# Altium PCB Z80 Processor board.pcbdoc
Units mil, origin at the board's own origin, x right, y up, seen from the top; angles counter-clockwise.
Board outline 3050 x 2500 mil, 4 copper layers (TopLayer, GroundPlane, PowerNetsPlane, BottomLayer); 36 components, 88 nets, 434 pads, 178 vias.
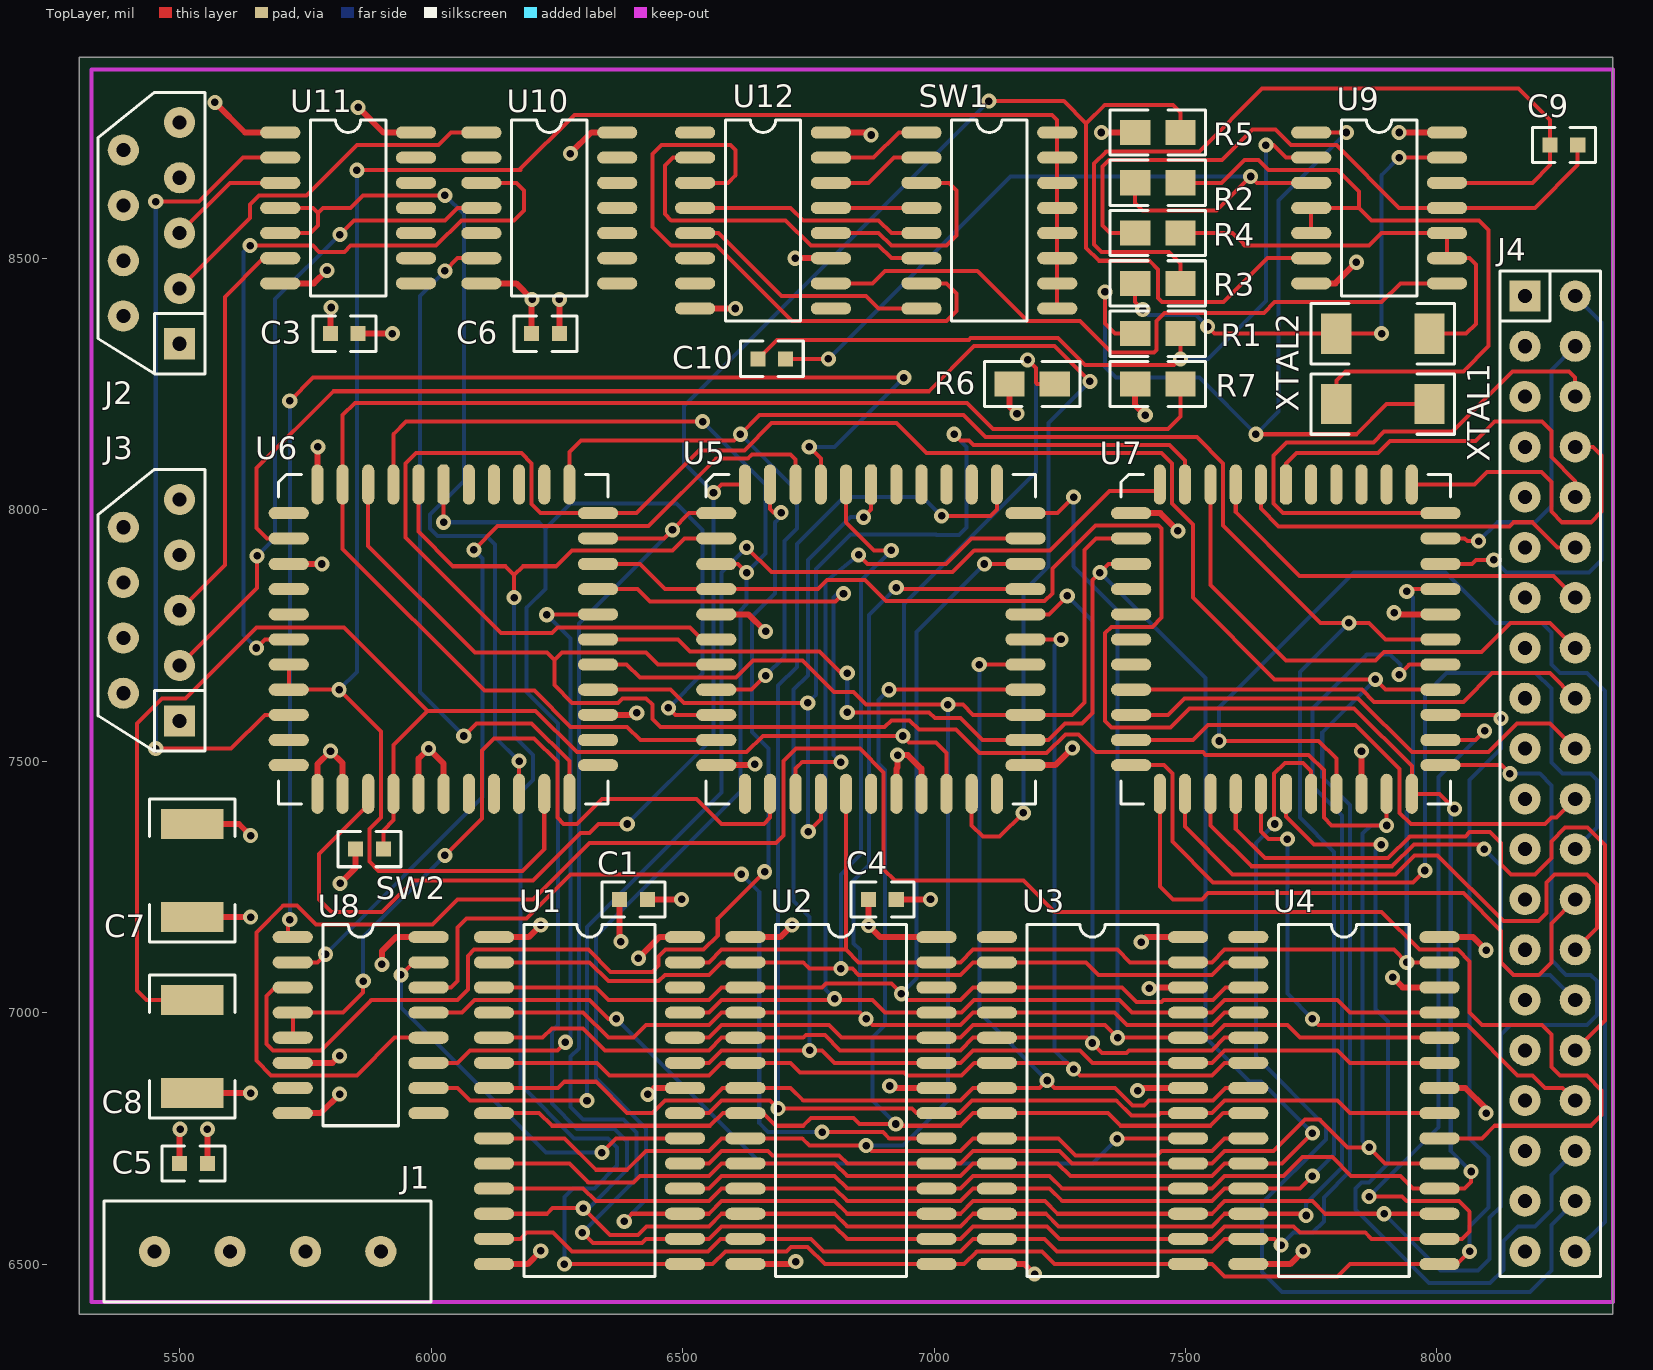
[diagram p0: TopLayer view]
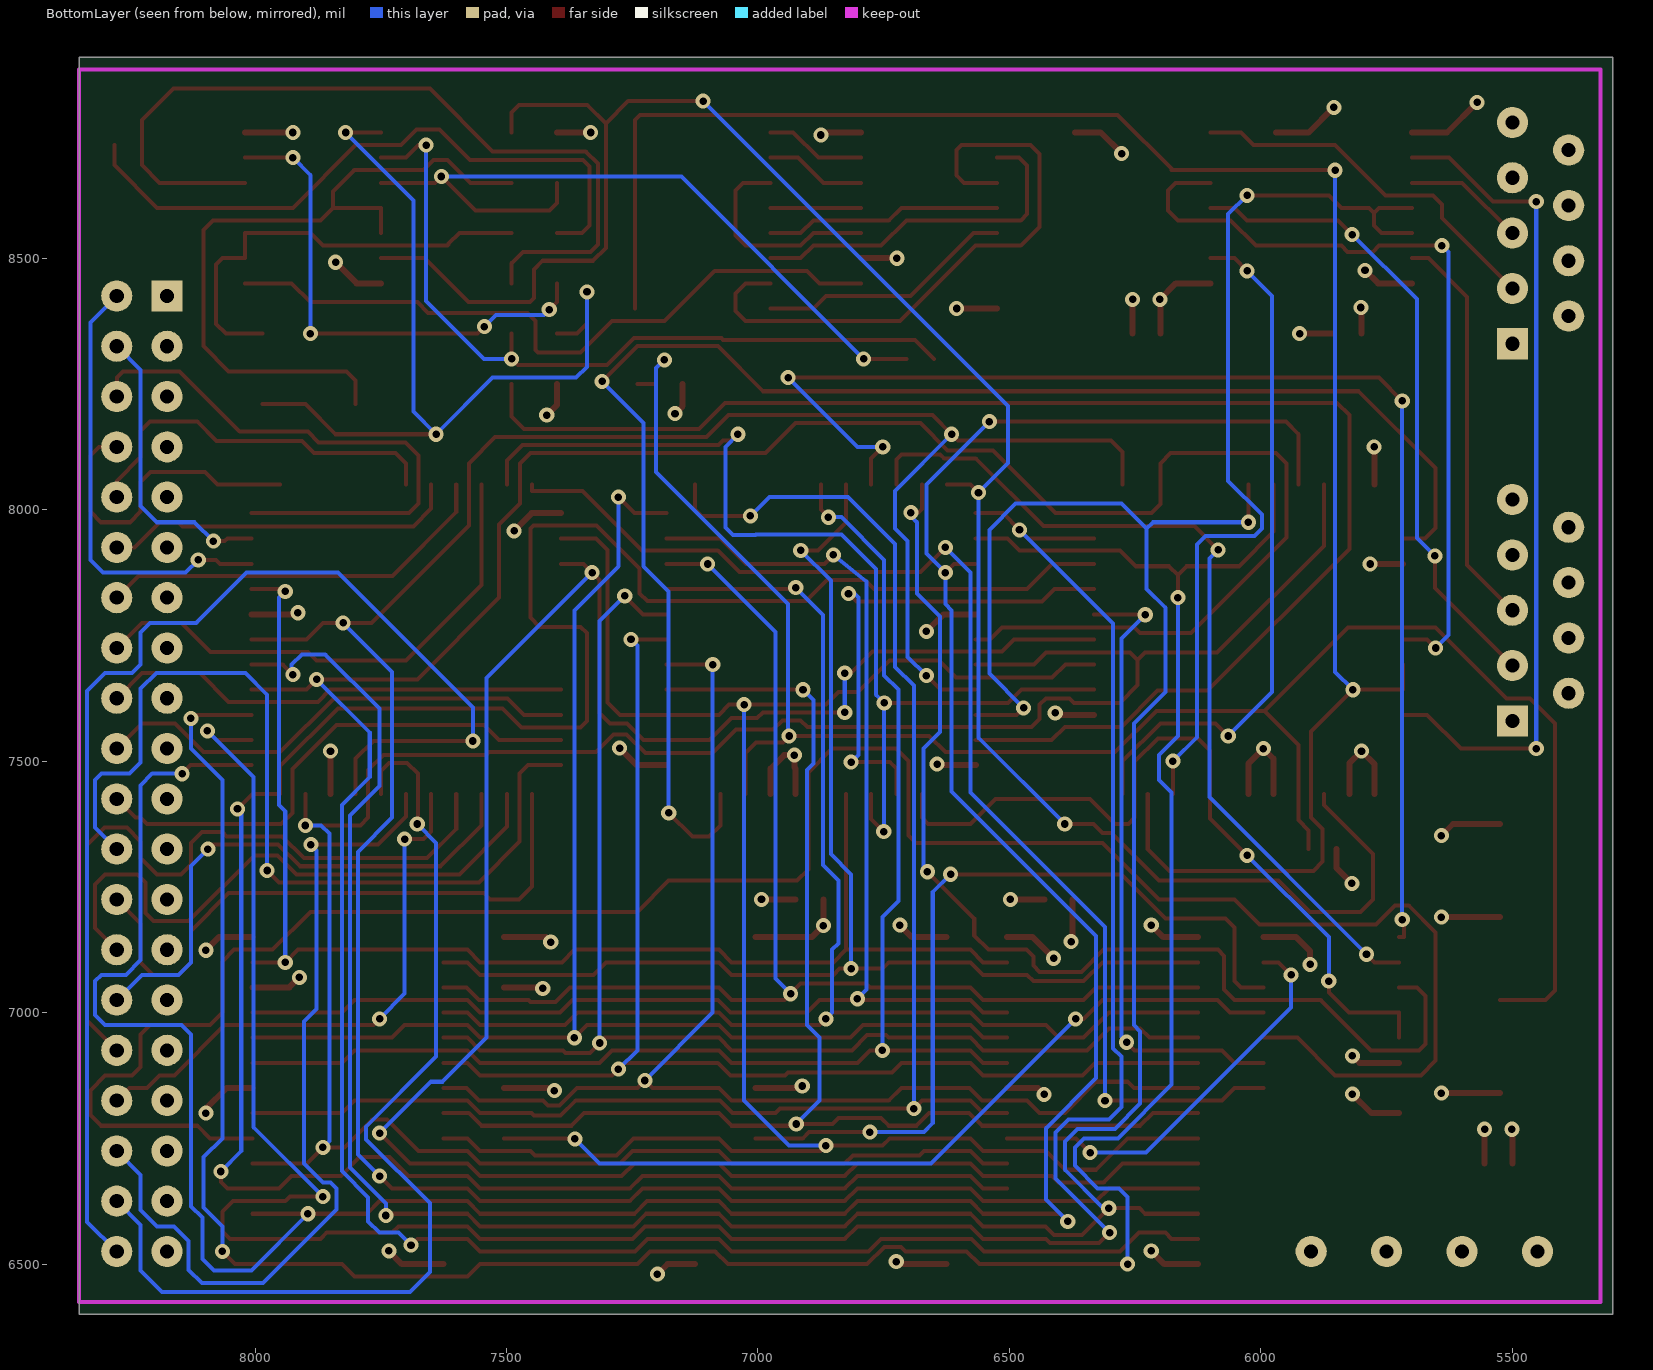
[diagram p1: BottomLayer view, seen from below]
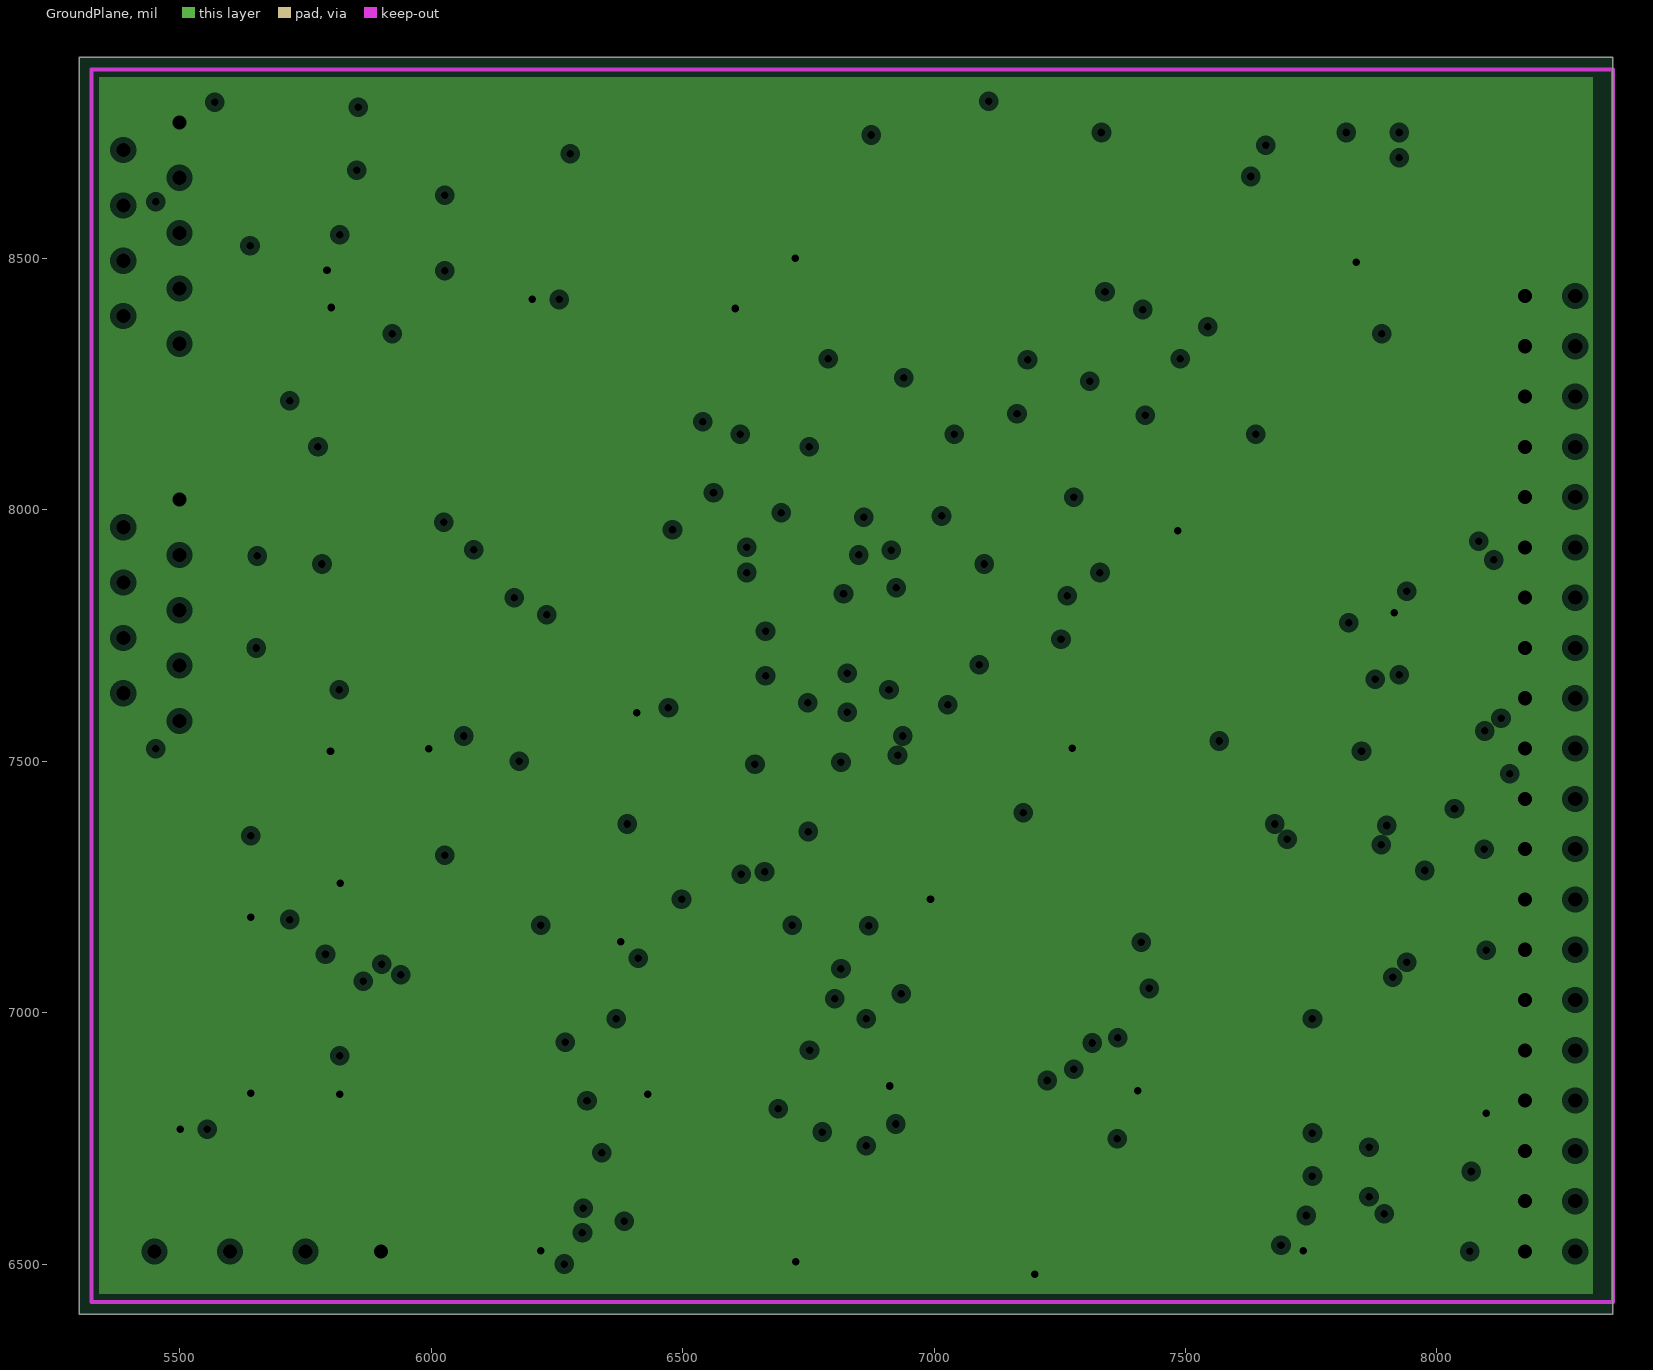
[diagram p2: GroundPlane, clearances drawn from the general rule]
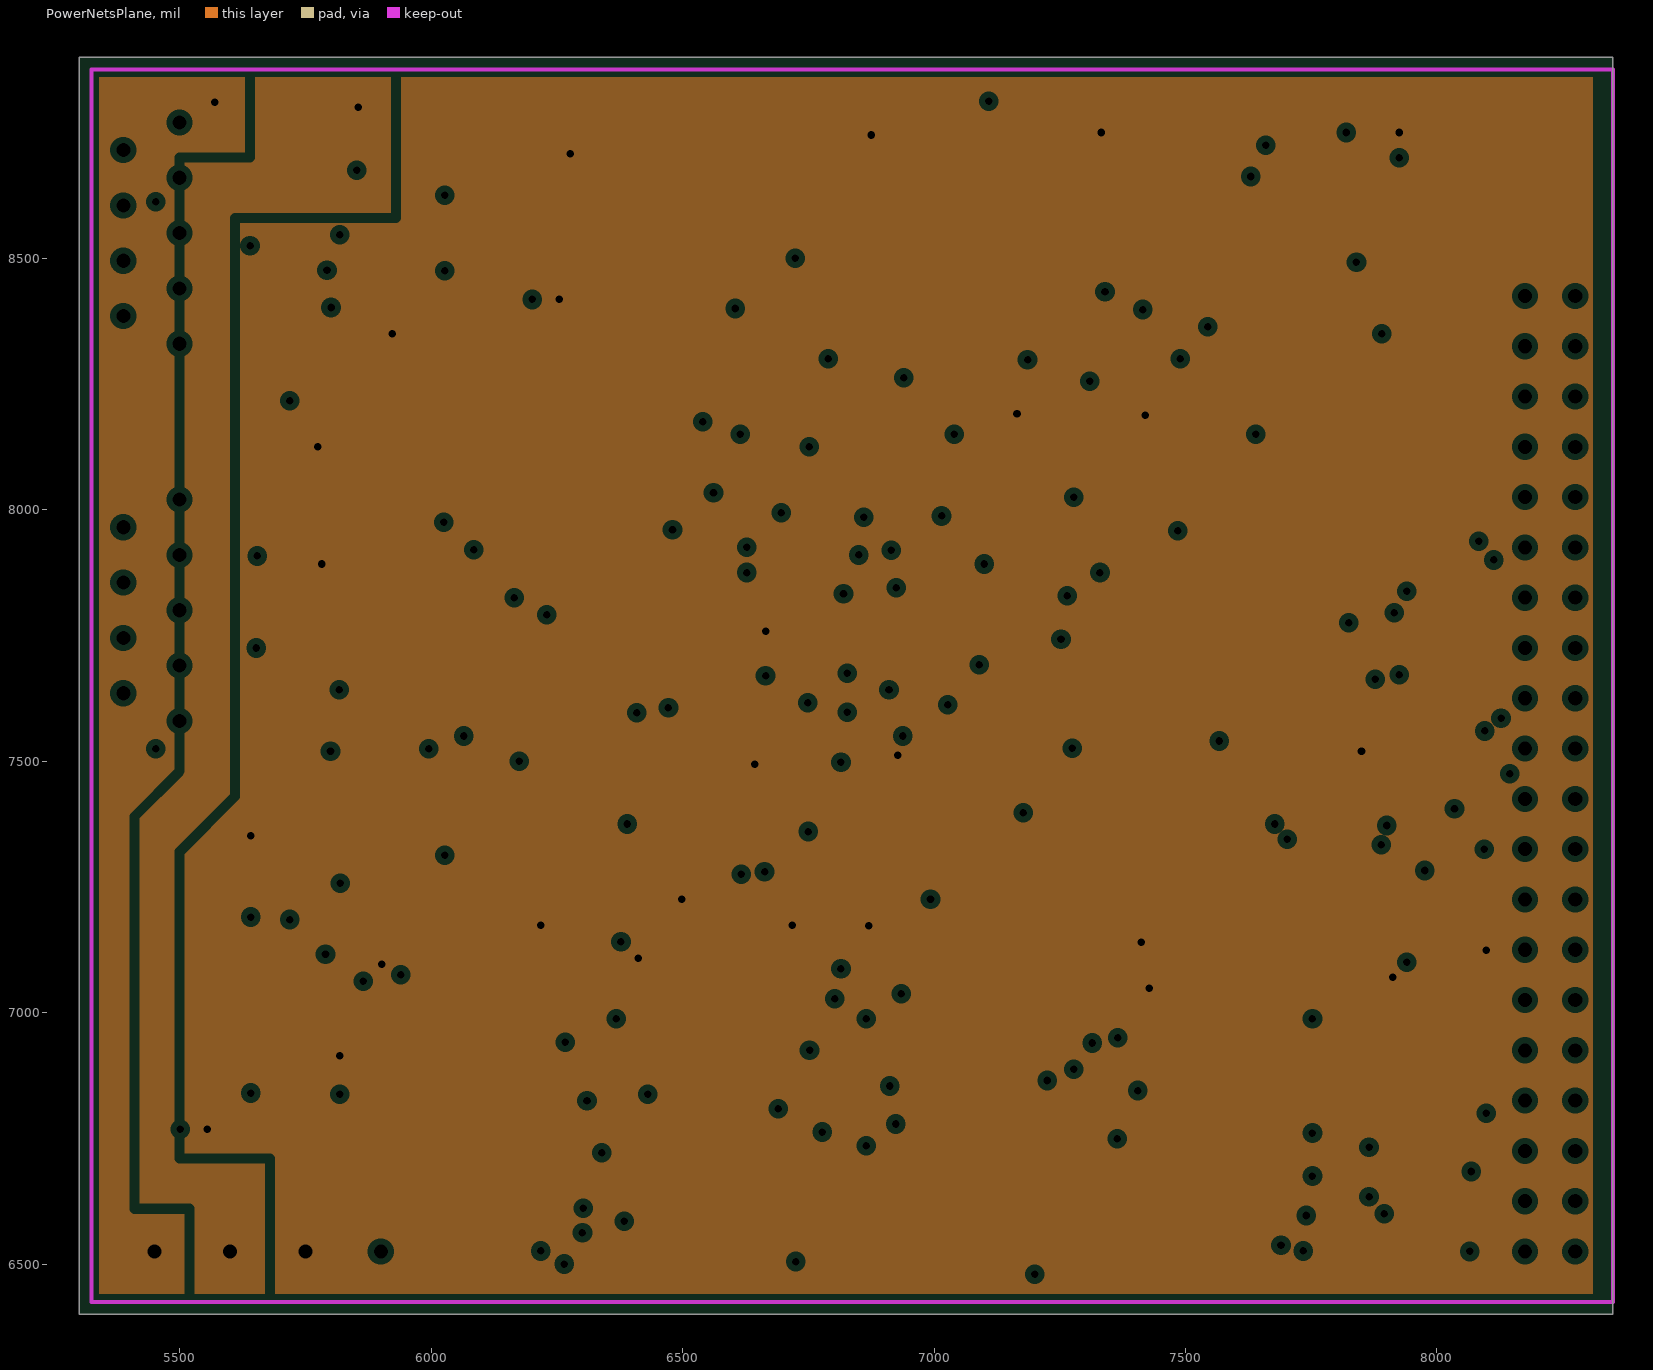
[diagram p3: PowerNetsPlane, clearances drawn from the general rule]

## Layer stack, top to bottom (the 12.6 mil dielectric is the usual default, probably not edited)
TopLayer: signal copper 1.4
Dielectric: core 12.6, FR-4, Dk 4.8
GroundPlane: plane copper 1.4, net GND
Dielectric: prepreg 12.6, FR-4, Dk 4.8
PowerNetsPlane: plane copper 1.4, net VCC
Dielectric: core 12.6, FR-4, Dk 4.8
BottomLayer: signal copper 1.4

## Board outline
5300,8900 5300,6400 8350,6400 8350,8900

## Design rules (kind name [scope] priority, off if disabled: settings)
Clearance "Polygon Clearance" [(IsPoly)] p1: gap=20
Clearance [All] p2: gap=8
ComponentClearance [All] p1: gap=10 collisioncheckmode=0
MaxMinImpedance MaxMinImped [All] p1: minimum=66.00 maximum=80.00
OvershootRising [All] p1: maximum=1.000
PlaneClearance [All] p1: clearance=12
PlaneConnect [All] p1: planeconnectstyle=Relief reliefexpansion=10 reliefentries=4 reliefconductorwidth=10 reliefairgap=10
PolygonConnect [All] p1: connectstyle=Relief reliefconductorwidth=10 reliefentries=4 polygonreliefangle="90 Angle"
RoutingLayers [All] p1: top layer=Horizontal bottom layer=Vertical
RoutingVias [All] p1: holewidth=15 width=30 viastyle="Through Hole" minholewidth=15 minwidth=30 maxholewidth=28 maxwidth=50
SolderMaskExpansion "SoldMask J1-1" [HasPad('J1-1')] p1: expansion=30
SolderMaskExpansion "SoldMask J1" [InComponent('J1')] p2: expansion=15
SolderMaskExpansion "SoldMask Board" [All] p3: expansion=5
SupplyNets "SupplyNet VCC" [InNet('VCC')] p1: voltage=5.000
SupplyNets "SupplyNet GND" [InNet('GND')] p2: voltage=0.000
SupplyNets "SupplyNet -12V" [InNet('-12')] p3: voltage=-12.00
SupplyNets "SupplyNet 12V" [InNet('+12')] p4: voltage=12.00
TestPointUsage [All] p1: valid=0 allowmultiple=FALSE
Testpoint [All] p1: side=15 testpointundercomponent=TRUE minsize=40 maxsize=100 preferedsize=60 minholesize=20 maxholesize=40 preferedholesize=32 testpointgrid=1 style=1023 order=1234567890
Width "Width +12V" [InNet('+12')] p1: maxlimit=12 minlimit=12 preferedwidth=12
Width "Width -12V" [InNet('-12')] p2: maxlimit=12 minlimit=12 preferedwidth=12
Width "Width GND" [InNet('GND')] p3: maxlimit=12 minlimit=12 preferedwidth=12
Width "Width VCC" [InNet('VCC')] p4: maxlimit=12 minlimit=12 preferedwidth=12
Width "Width Board" [All] p5: maxlimit=8 minlimit=8 preferedwidth=8
14 further rules are at their usual default settings.

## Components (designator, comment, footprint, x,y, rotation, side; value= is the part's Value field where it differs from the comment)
C1 "0.1uF" 0603 6375,7225 r0 top
C3 "0.1uF" 0603 5800,8350 r0 top
C4 "0.1uF" 0603 6925,7225 r180 top
C5 "0.1uF" 0603 5500,6700 r0 top
C6 "0.1uF" 0603 6200,8350 r0 top
C7 "100uF" 1812 5525,7375 r270 top
C8 "10uF" 1812 5525,7025 r270 top
C9 "0.1uF" 0603 8225,8725 r0 top
C10 "0.1uF" 0603 6650,8300 r0 top
J1 "4PIN" FLY4 5900,6525 r180 top
J2 "DB9" DB9 5500,8325 r90 top
J3 "DB9" DB9 5500,7575 r90 top
J4 "40 PIN" IDC40 8175,8425 r270 top
R1 "470R" 0805 7400,8350 r0 top
R2 "470R" 0805 7400,8650 r0 top
R3 "470R" 0805 7400,8450 r0 top
R4 "470R" 0805 7400,8550 r0 top
R5 "330R" 0805 7400,8750 r0 top
R6 "4k7" 0805 7150,8250 r0 top
R7 "4k7" 0805 7400,8250 r0 top
SW1 "DIPSW8" SOJ-16 6975,8750 r0 top
SW2 "PUSH" 0603 5850,7325 r0 top
U1 "2764" SOL-28 6125,7150 r0 top
U2 "2764" SOL-28 6625,7150 r0 top
U3 "6264" SOL-28 7125,7150 r0 top
U4 "6264" SOL-28 7625,7150 r0 top
U5 "Z80ACPU" PJLCC44 6875,8050 r0 top
U6 "Z80ASIO" PJLCC44 6025,8050 r0 top
U7 "8255" PJLCC44 7700,8050 r0 top
U8 "74ACT138" SOJ-16 5725,7150 r0 top
U9 "SN74ACT04N" SOJ-14 7750,8750 r0 top
U10 "TS1489" SOJ-14 6100,8750 r0 top
U11 "TS1488" SOJ-14 5700,8750 r0 top
U12 "SN74HC4040D" SOJ-16 6525,8750 r0 top
XTAL1 "4.00 MHz" 1808 7985,8210 r180 top
XTAL2 "4.915 MHz" 1808 7800,8350 r0 top

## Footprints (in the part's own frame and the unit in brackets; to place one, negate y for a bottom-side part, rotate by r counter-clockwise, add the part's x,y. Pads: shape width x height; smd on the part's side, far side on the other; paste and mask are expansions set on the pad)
0603 [mil]
  rect 30x30 smd: 1(0,0) 2(55,0)
  silkscreen extent -35,-35 90,35
0805 [mil]
  rect 60x50 smd: 1(0,0) 2(90,0)
  silkscreen extent -50,-45 140,45
1808 [mil]
  rect 60x80 smd: 1(0,0) 2(185,0)
  silkscreen extent -50,-60 235,60
1812 [mil]
  rect 60x125 smd: 1(0,0) 2(185,0)
  silkscreen extent -50,-85 235,85
DB9 [mil]
  rect 62x62 hole 28: 1(5,0)
  round 62 hole 28: 2(115,0) 3(225,0) 4(335,0) 5(445,0) 6(60,112) 7(170,112) 8(280,112) 9(390,112)
  silkscreen extent -55,-50 505,162
FLY4 [mil]
  round 62 hole 28: 1(0,0) 2(150,0) 3(300,0) 4(450,0)
  silkscreen extent -100,-100 550,100
IDC40 [mil]
  rect 62x62 hole 28: 1(0,0)
  round 62 hole 28: 2(0,100) 3(100,0) 4(100,100) 5(200,0) 6(200,100) 7(300,0) 8(300,100) 9(400,0) 10(400,100) 11(500,0) 12(500,100) 13(600,0) 14(600,100) 15(700,0) 16(700,100) 17(800,0) 18(800,100) 19(900,0) 20(900,100) 21(1000,0) 22(1000,100) 23(1100,0) 24(1100,100) 25(1200,0) 26(1200,100) 27(1300,0) 28(1300,100) 29(1400,0) 30(1400,100) 31(1500,0) 32(1500,100) 33(1600,0) 34(1600,100) 35(1700,0) 36(1700,100) 37(1800,0) 38(1800,100) 39(1900,0) 40(1900,100)
  silkscreen extent -50,-50 1950,150
PJLCC44 [mil]
  oct 24x80 smd: 1(0,0)
  oval 24x80 smd: 2(-50,0) 3(-100,0) 4(-150,0) 5(-201,0) 6(-251,0) 18(-251,-615) 19(-201,-615) 20(-150,-615) 21(-100,-615) 22(-50,-615) 23(0,-615) 24(50,-615) 25(100,-615) 26(150,-615) 27(200,-615) 28(250,-615) 40(250,0) 41(200,0) 42(150,0) 43(100,0) 44(50,0)
  oval 80x24 smd: 7(-308,-57) 8(-308,-107) 9(-308,-158) 10(-308,-208) 11(-308,-258) 12(-308,-308) 13(-308,-358) 14(-308,-408) 15(-308,-458) 16(-308,-508) 17(-308,-558) 29(307,-558) 30(307,-508) 31(307,-458) 32(307,-408) 33(307,-358) 34(307,-308) 35(307,-258) 36(307,-208) 37(307,-158) 38(307,-107) 39(307,-57)
  silkscreen extent -328,-635 327,20
SOJ-14 [mil]
  oval 80x24 smd: 1(0,0) 2(0,-50) 3(0,-100) 4(0,-150) 5(0,-200) 6(0,-250) 7(0,-300) 8(270,-300) 9(270,-250) 10(270,-200) 11(270,-150) 12(270,-100) 13(270,-50) 14(270,0)
  silkscreen extent 60,-325 210,25
SOJ-16 [mil]
  oval 80x24 smd: 1(0,0) 2(0,-50) 3(0,-100) 4(0,-150) 5(0,-200) 6(0,-250) 7(0,-300) 8(0,-350) 9(270,-350) 10(270,-300) 11(270,-250) 12(270,-200) 13(270,-150) 14(270,-100) 15(270,-50) 16(270,0)
  silkscreen extent 60,-375 210,25
SOL-28 [mil]
  oval 80x24 smd: 1(0,0) 2(0,-50) 3(0,-100) 4(0,-150) 5(0,-200) 6(0,-250) 7(0,-300) 8(0,-350) 9(0,-400) 10(0,-450) 11(0,-500) 12(0,-550) 13(0,-600) 14(0,-650) 15(380,-650) 16(380,-600) 17(380,-550) 18(380,-500) 19(380,-450) 20(380,-400) 21(380,-350) 22(380,-300) 23(380,-250) 24(380,-200) 25(380,-150) 26(380,-100) 27(380,-50) 28(380,0)
  silkscreen extent 60,-675 320,25

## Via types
v1: diameter 30, hole 15, TopLayer to BottomLayer, 178 vias

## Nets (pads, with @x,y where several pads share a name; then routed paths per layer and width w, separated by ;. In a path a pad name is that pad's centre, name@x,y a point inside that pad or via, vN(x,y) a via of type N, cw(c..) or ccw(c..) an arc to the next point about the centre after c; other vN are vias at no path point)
75: SW1.1 U12.15 | length 200.7
  TopLayer w8: U12.15 6880,8700 6930,8750 SW1.1
150: SW1.2 U12.14 | length 200.7
  TopLayer w8: U12.14 6870,8650 6920,8700 SW1.2
300: SW1.3 U12.12 | length 434.9
  TopLayer w8: U12.12 6890,8550 6915,8525 7025,8525 7045,8545 7045,8635 7030,8650 SW1.3
600: SW1.4 U12.13 | length 180
  TopLayer w8: U12.13 SW1.4
1200: SW1.5 U12.4 | length 470.7
  TopLayer w8: U12.4 6715,8600 6740,8575 6890,8575 6915,8550 SW1.5
4800: SW1.6 U12.2 | length 709.4
  TopLayer w8: U12.2 6481,8700 6465,8684 6465,8587.5 6477.5,8575 6705,8575 6755,8525 6890,8525 6915,8500 SW1.6
9600: SW1.7 U12.3 | length 1261.3
  TopLayer w8: U12.3 6590,8650 6605,8665 6605,8715 6595,8725 6458,8725 6440,8707 6440,8562.5 6477.5,8525 6567.5,8525 6717.5,8375 7024.5,8375 7045,8395.5 7045,8430 7025,8450 SW1.7
19200: SW1.8 U12.5 | length 512.1
  TopLayer w8: U12.5 6571.5,8550 6696.5,8425 6865,8425 6890,8400 SW1.8
+12: J1.3 U11.14 | length 135.7
  TopLayer w12: v1(5855,8800) 5905,8750 U11.14
-12: J1.4 U11.1 | length 154.9
  TopLayer w12: v1(5570,8810) 5630,8750 U11.1
A0: U1.10 U2.10 U3.10 U4.10 U5.30 U6.34 U7.9 | length 4516.2
  TopLayer w8: U1.10 6275,6700 6312.5,6662.5 6402.5,6662.5 6415,6675 6552.5,6675 6577.5,6700 U2.10 6802.5,6700 6827.5,6675 7052.5,6675 7077.5,6700 U3.10 7246,6700 7271,6675 7552.5,6675 7577.5,6700 U4.10 7692,6700 v1(7752.5,6760.5) ; U6.34 6491,7742 6515,7718 6772,7718 6815,7675 v1(6827.5,7675) ; v1(6827.5,7597) 6990,7597 7001.5,7585.5 7052.5,7585.5 7096,7542 U5.30 7227.37,7542 7260.37,7575 7294,7575 7315,7596 7315,7860 v1(7330,7875) 7347,7892 U7.9
  BottomLayer w8: v1(6827.5,7597) v1(6827.5,7675) ; v1(7330,7875) 7540,7665 7540,6950 7627.5,6862.5 7650.5,6862.5 v1(7752.5,6760.5)
A1: U1.9 U2.9 U3.9 U4.9 U5.31 U6.33 U7.8 | length 4040.2
  TopLayer w8: U1.9 6265,6750 6327.5,6687.5 6390,6687.5 6427.5,6725 6552.5,6725 6577.5,6750 U2.9 6738,6750 6752.5,6735.5 v1(6865,6735.5) 6875.5,6725 7052.5,6725 7077.5,6750 U3.9 7247.13,6750 7281.13,6716 7443.5,6716 7452.5,6725 7552.5,6725 7577.5,6750 U4.9 ; U6.33 6389,7692 6415,7666 6606,7666 6640,7700 6738.5,7700 6801,7637.5 6840,7637.5 6864.5,7613 7027,7613 v1(7027.5,7612.5) 7057.5,7612.5 7078,7592 U5.31 7274,7592 7299,7617 7299,7920 7322,7943 U7.8
  BottomLayer w8: v1(6865,6735.5) 6938,6735.5 7027.5,6825 v1(7027.5,7612.5)
A2: U1.8 U2.8 U3.8 U4.8 U5.32 | length 2752.8
  TopLayer w8: U1.8 6215,6800 6240,6775 6555,6775 6580,6800 U2.8 6660,6800 6685,6775 6740,6775 6755,6790 6840,6790 6851.5,6778.5 v1(6924,6778.5) 6927.5,6775 7052.5,6775 7077.5,6800 U3.8 7346.28,6800 7371.28,6775 7550.13,6775 7575.13,6800 U4.8 ; v1(6910.5,7642) U5.32
  BottomLayer w8: v1(6910.5,7642) 6890,7621.5 6890,7495 6902.5,7482.5 6902.5,6975 6877.5,6950 6877.5,6825 v1(6924,6778.5)
A3: U1.7 U2.7 U3.7 U4.7 U5.33 | length 2588.8
  TopLayer w8: U1.7 6252.5,6850 6265,6862.5 6327.5,6862.5 6390,6800 6440,6800 6465,6825 6554.5,6825 6579.5,6850 6715,6850 6740,6825 7052.5,6825 7077.5,6850 7210,6850 v1(7225,6865) 7240,6850 7360,6850 7395,6815 7417.37,6815 7427.37,6825 7554.5,6825 7579.5,6850 U4.7 ; v1(7090,7692) U5.33
  BottomLayer w8: v1(7090,7692) 7090,7000 v1(7225,6865)
A4: U1.6 U2.6 U3.6 U4.6 U5.34 | length 2507.8
  TopLayer w8: U1.6 6330,6900 6355,6875 6552.5,6875 6577.5,6900 U2.6 6715,6900 6734,6881 6940,6881 6946,6875 7055,6875 7080,6900 U3.6 7265,6900 v1(7277.5,6887.5) 7290,6875 7552.5,6875 7577.5,6900 U4.6 ; U5.34 v1(7252.5,7742)
  BottomLayer w8: v1(7252.5,7742) 7240,7729.5 7240,6925 v1(7277.5,6887.5)
A5: U1.5 U2.5 U3.5 U4.5 U5.35 | length 2593.6
  TopLayer w8: U1.5 6221.5,6950 6240,6968.5 6302.5,6968.5 6346,6925 6552.5,6925 6577.5,6950 U2.5 6740,6950 6745,6955 6783,6955 6813,6925 7052.5,6925 7077.5,6950 U3.5 7304.5,6950 v1(7315,6939.5) 7334.5,6920 7382.5,6920 7387.5,6925 7552.5,6925 7577.5,6950 U4.5 ; U5.35 7228.5,7792 v1(7265,7828.5)
  BottomLayer w8: v1(7265,7828.5) 7315,7778.5 v1(7315,6939.5)
A6: U1.4 U2.4 U3.4 U4.4 U5.36 | length 2744.1
  TopLayer w8: U1.4 6302.5,7000 6352.5,6950 6402.5,6950 6427.5,6975 6552.5,6975 6577.5,7000 U2.4 6852.5,7000 v1(6865,6987.5) 6877.5,6975 7052.5,6975 7077.5,7000 U3.4 7359,7000 7384,6975 7552.5,6975 7577.5,7000 U4.4 ; v1(6925,7845) 6928,7842 U5.36
  BottomLayer w8: v1(6865,6987.5) 6852.5,7000 6852.5,7125 6840,7137.5 6840,7262.5 6871,7293.5 6871,7791 v1(6925,7845)
A7: U1.3 U2.3 U3.3 U4.3 U5.37 | length 2576.5
  TopLayer w8: U1.3 6327.5,7050 6352.5,7025 6552.5,7025 6577.5,7050 U2.3 6777.5,7050 6785,7057.5 6915,7057.5 v1(6935,7037.5) 6947.5,7025 7052.5,7025 7077.5,7050 U3.3 7373.5,7050 7402.5,7021 7452.5,7021 7456.5,7025 7554.5,7025 7579.5,7050 U4.3 ; v1(7100,7892) U5.37
  BottomLayer w8: v1(6935,7037.5) 6965,7067.5 6965,7757 v1(7100,7892)
A8: U1.25 U2.25 U3.25 U4.25 U5.38 | length 2846
  TopLayer w8: U1.25 6552.5,7000 6577.5,7025 6800,7025 v1(6802.5,7027.5) 6805,7025 6877.5,7025 6902.5,7000 U2.25 7054.5,7000 7079.5,7025 7368.5,7025 7393.5,7000 U3.25 7552.5,7000 7577.5,7025 7802.5,7025 7827.5,7000 U4.25 ; v1(6850,7910) 6868,7892 7024,7892 7075,7943 U5.38
  BottomLayer w8: v1(6802.5,7027.5) 6784.5,7045.5 6784.5,7857 v1(6850,7910)
A9: U1.24 U2.24 U3.24 U4.24 U5.39 | length 2782.1
  TopLayer w8: U1.24 6552.5,6950 6577.5,6975 6791.5,6975 6816.5,6950 U2.24 7052.5,6950 7077.5,6975 7340,6975 v1(7365,6950) U3.24 7552.5,6950 7577.5,6975 7702.5,6975 7727.5,6950 U4.24 ; U5.39 7245.5,7993 v1(7277.5,8025)
  BottomLayer w8: v1(7277.5,8025) 7277.5,7887.5 7365,7800 v1(7365,6950)
A10: U1.21 U2.21 U3.21 U4.21 U5.40 | length 3211.2
  TopLayer w8: U1.21 6552.5,6800 6577.5,6825 6674,6825 v1(6690,6809) 6956,6809 6965,6800 7050.5,6800 7075.5,6825 7362.37,6825 7392.37,6795 7445,6795 7450,6800 7552.5,6800 7577.5,6825 7802.5,6825 7827.5,6800 U4.21 ; v1(7015,7987.5) 7112.5,7987.5 7125,8000 U5.40
  BottomLayer w8: v1(6690,6809) 6690,7650 6727.5,7687.5 6727.5,7931.5 6821,8025 6977.5,8025 v1(7015,7987.5)
A11: U1.23 U2.23 U3.23 U4.23 U5.1 | length 2779.2
  TopLayer w8: U1.23 6552.5,6900 6577.5,6925 v1(6752.5,6925) 6777.5,6925 6802.5,6900 U2.23 7052.5,6900 7077.5,6925 7290,6925 7315,6900 U3.23 7552.5,6900 7577.5,6925 7802.5,6925 7827.5,6900 U4.23 ; v1(6860,7985) 6875,8000 U5.1
  BottomLayer w8: v1(6752.5,6925) 6752.5,7190 6721,7221.5 6721,7642.5 6749,7670.5 6749,7900 6834,7985 v1(6860,7985)
A12: U1.2 U2.2 U3.2 U4.2 U5.2 | length 2633.6
  TopLayer w8: U1.2 6315,7100 6352.5,7062.5 6452.5,7062.5 6465,7075 6552.5,7075 6577.5,7100 U2.2 6740,7100 6752.5,7087.5 v1(6815,7087.5) 6837.5,7087.5 6850,7075 7052.5,7075 7077.5,7100 U3.2 7302.5,7100 7327.5,7075 7552.5,7075 7577.5,7100 U4.2 ; U5.2 6825,7975 6881,7919 v1(6915,7919)
  BottomLayer w8: v1(6815,7087.5) 6815,7275 6855,7315 6855,7859 v1(6915,7919)
A13: U5.3 U8.1 | length 2648.6
  TopLayer w8: v1(5719,7185) 5717.5,7185 5715,7182.5 5715,7150 U8.1 ; v1(5719,8216.5) 5765,8262.5 v1(6940,8262.5) ; v1(6752,8125) 6775,8102 U5.3
  BottomLayer w8: v1(5719,7185) v1(5719,8216.5) ; v1(6752,8125) 6802.5,8125 v1(6940,8262.5)
A14: U5.4 U8.2 | length 1785.2
  TopLayer w8: U8.2 5774,7100 v1(5790,7116) ; v1(6085,7920) 6132.5,7967.5 6432.5,7967.5 6567,8102 6629.63,8102 6637.63,8110 6715,8110 6725,8100 U5.4
  BottomLayer w8: v1(5790,7116) 6102.5,7428.5 6102.5,7902.5 v1(6085,7920)
A15: U5.5 U8.3 | length 2231.8
  TopLayer w8: U8.3 5690,7050 5673,7033 5673,6937.5 5685.5,6925 5781,6925 5881,7025 6052.5,7025 6073,7045.5 6073,7112.5 6085.5,7125 6312.63,7125 6356.63,7081 6440,7081 6452.5,7093.5 6452.5,7111.5 6466,7125 6542,7125 6570,7153 6570,7187 v1(6663,7280) ; U5.5 6674,8001 6681,7994 v1(6696,7994)
  BottomLayer w8: v1(6663,7280) 6671,7288 6671,7525 6638,7558 6638,7787.5 6683.5,7833 6683.5,7975 6696,7987.5 v1(6696,7994)
CPUCLK: R5.2 U5.6 U6.20 U9.6 | length 4070
  TopLayer w8: U6.20 5875,7412.5 5777.5,7315 5777.5,7224.5 5802,7200 5902.5,7200 5965,7262.5 6202.5,7262.5 6297,7357 6315,7357 6333,7375 v1(6390,7375) ; v1(6561.5,8034) 6577.5,8050 U5.6 ; v1(7109,8812.5) 7258,8812.5 7302.5,8768 ; R5.2 7490,8790 7475,8805 7339.5,8805 7302.5,8768 ; U9.6 7663.5,8500 7576,8412.5 7453,8412.5 7445,8420.5 7445,8478 7428,8495 7328,8495 7302.5,8520.5 7302.5,8768
  BottomLayer w8: v1(6390,7375) 6561.5,7546.5 v1(6561.5,8034) 6502.5,8093 6502.5,8206 v1(7109,8812.5)
D0: U1.11 U2.11 U3.11 U4.11 U5.14 U6.40 U7.34 | length 5632.5
  TopLayer w8: U1.11 6302.5,6650 6327.5,6625 6552.5,6625 6577.5,6650 U2.11 6802.5,6650 6827.5,6625 7052.5,6625 7077.5,6650 U3.11 7230,6650 7255,6625 7552.5,6625 7577.5,6650 U4.11 7727.5,6650 v1(7752.5,6675) ; U6.40 6275,8114.5 6298,8137.5 6602.5,8137.5 v1(6615,8150) 6653,8188 7059,8188 7102.5,8144.5 7522.5,8144.5 7575,8092 7575,7968.5 7768.5,7775 v1(7825,7775) 7865,7775 7898,7742 U7.34 ; U5.14 6637,7642 v1(6665,7670)
  BottomLayer w8: v1(6615,8150) 6727.5,8037.5 6727.5,7962.5 6702.5,7937.5 6702.5,7707.5 v1(6665,7670) ; v1(7752.5,6675) 7795.5,6718 7795.5,7319.5 7727.5,7387.5 7727.5,7677.5 v1(7825,7775)
D1: U1.12 U2.12 U3.12 U4.12 U5.15 U6.1 U7.33 | length 5771.2
  TopLayer w8: v1(6025,7975) U6.1 ; U1.12 6230,6600 6241,6611 v1(6302.5,6611) 6356,6557.5 6411,6557.5 6428.5,6575 6552.5,6575 6577.5,6600 U2.12 6802.5,6600 6827.5,6575 7052.5,6575 7077.5,6600 U3.12 7222.63,6600 7247.63,6575 7552.5,6575 7577.5,6600 U4.12 7736.5,6600 v1(7740,6596.5) ; v1(6472,7606) 6486,7592 U5.15 ; v1(7925,7672) 7945,7692 U7.33
  BottomLayer w8: v1(6025,7975) 6215,7975 6227.5,7962.5 ; v1(6302.5,6611) 6313.5,6611 6390,6687.5 6390,6744 6365,6769 6290,6769 6240,6819 6240,6962.5 6252.5,6975 6252.5,7575 6190,7637.5 6190,7805 6227.5,7842.5 6227.5,7962.5 ; v1(6472,7606) 6540,7674 6540,7960 6487.5,8012.5 6277.5,8012.5 6227.5,7962.5 ; v1(7740,6596.5) 7740,6620 7811.5,6691.5 7811.5,7391.5 7752.5,7450.5 7752.5,7604.5 7860.5,7712.5 7907,7712.5 7927.5,7692 7927.5,7674.5 v1(7925,7672)
D2: U1.13 U2.13 U3.13 U4.13 U5.12 U6.39 U7.32 | length 6360.4
  TopLayer w8: U1.13 6177.5,6550 6190,6562.5 6242.5,6562.5 6280,6525 6550.13,6525 6575.13,6550 U2.13 6755.5,6550 6780.5,6525 7052.5,6525 7077.5,6550 U3.13 7220,6550 7245,6525 7552.5,6525 7577.5,6550 U4.13 7677.5,6550 v1(7690,6537.5) ; U5.12 6539,7742 6515,7766 6251,7766 6240,7755 6139,7755 5949,7945 5949,8092 5969.5,8112.5 6179.5,8112.5 6200,8092 6200,8011 6218,7993 U6.39 6408,7993 6533,8118 6623,8118 6677,8172 6925.5,8172 6985,8112.5 7452.5,8112.5 7473,8092 7473,8012.5 7515,7970.5 7515,7825 7677.5,7662.5 v1(7877.5,7662.5) 7898,7642 U7.32
  BottomLayer w8: v1(7690,6537.5) 7715,6562.5 7752.5,6562.5 7775,6585 7775,6632.37 7827.5,6684.87 7827.5,7412.5 7772,7468 7772,7557 v1(7877.5,7662.5)
D3: U1.15 U2.15 U3.15 U4.15 U5.8 U6.2 U7.31 | length 5455.4
  TopLayer w8: U6.2 5975,7956.5 6044,7887.5 6147.5,7887.5 6165,7870 ; v1(6165,7825) 6165,7870 ; v1(6265,6500) 6560,6500 6585,6525 6706.86,6525 6715.86,6534 6748.87,6534 6782.87,6500 7060,6500 7085,6525 7215,6525 7240,6500 U3.15 7552.5,6500 7577.5,6475 7802.5,6475 7827.5,6500 8040,6500 v1(8065,6525) ; U5.8 6504,7943 6480,7919 6280,7919 6248.5,7887.5 6182.5,7887.5 6165,7870 ; U7.31 8120.5,7592 v1(8127.5,7585)
  BottomLayer w8: v1(6165,7825) 6165,7550 6202.5,7512.5 6202.5,7462.5 6177.5,7437.5 6177.5,6857 6284.5,6750 6352,6750 6370,6732 6370,6695.5 6324.5,6650 6282,6650 6265,6633 v1(6265,6500) ; v1(8065,6525) 8065,6575 8102.5,6612.5 8102.5,6712.5 8065,6750 8065,7462.5 8127.5,7525 v1(8127.5,7585)
D4: U1.16 U2.16 U3.16 U4.16 U5.7 U6.38 U7.30 | length 5095.8
  TopLayer w8: v1(6301,6562.5) 6322,6541.5 6419,6541.5 6427.5,6550 U1.16 6552.5,6550 6577.5,6575 6802.5,6575 6827.5,6550 U2.16 7052.5,6550 7077.5,6575 7225,6575 7250,6550 U3.16 7552.5,6550 7577.5,6575 7715,6575 7727.5,6562.5 7857.5,6562.5 7870,6550 U4.16 8050,6550 8065,6565 8065,6604 8044,6625 7940,6625 7931,6634 v1(7865,6634) ; U6.38 6463,7943 v1(6480,7960) 6513,7993 U5.7 ; U7.30 8077,7542 v1(8095,7560)
  BottomLayer w8: v1(6301,6562.5) 6408.5,6670 6408.5,6762 6383,6787.5 6302.5,6787.5 6277.5,6812.5 6277.5,6912.5 6294,6929 6294,7774 v1(6480,7960) ; v1(7865,6634) 8003,6772 8003,7468 v1(8095,7560)
D5: U1.17 U2.17 U3.17 U4.17 U5.9 U6.3 U7.29 | length 6010.8
  TopLayer w8: U6.3 5925,8150 5950,8175 v1(6540,8175) ; v1(6384,6585) 6399,6600 U1.17 6552.5,6600 6577.5,6625 6802.5,6625 6827.5,6600 U2.17 7052.5,6600 7077.5,6625 7220.25,6625 7245.25,6600 U3.17 7552.5,6600 7577.5,6625 7752.5,6625 7777.5,6600 v1(7895,6600) U4.17 ; U5.9 6610.5,7892 v1(6627.5,7875) ; U7.29 8128,7492 v1(8145,7475)
  BottomLayer w8: v1(6384,6585) 6427.5,6628.5 6427.5,6770 6327.5,6870 6327.5,7152.5 6615,7440 6615,7800 6627.5,7812.5 v1(6627.5,7875) 6665,7912.5 6665,8050 v1(6540,8175) ; v1(7895,6600) 8007.5,6487.5 8082,6487.5 8105,6510.5 8105,6592.37 8127.5,6614.87 8127.5,6956 8146.5,6975 8298,6975 8318,6995 8318,7062.5 8305.5,7075 8257,7075 8227.5,7104.5 8227.5,7452 8204.5,7475 v1(8145,7475)
D6: U1.18 U2.18 U3.18 U4.18 U5.10 U6.37 U7.28 | length 4995.1
  TopLayer w8: U6.37 6415,7892 6465,7842 U5.10 6769.5,7842 6787.5,7860 6863,7860 6905,7818 7220,7818 7235.5,7833.5 7235.5,7883 7321.5,7969 7446,7969 7452.5,7962.5 7452.5,7785.5 7434,7767 7352.5,7767 7340,7754.5 7340,7579.5 7352.5,7567 7470,7567 7508,7605 7835,7605 7950,7490 U7.28 8005,7435 v1(8035,7405) ; U1.18 6552.5,6650 6577.5,6675 6802.5,6675 6827.5,6650 U2.18 7052.5,6650 7077.5,6675 7230,6675 7255,6650 U3.18 7552.5,6650 7577.5,6675 7695,6675 7732.5,6712.5 7792,6712.5 7829.5,6675 7927.5,6675 7952.5,6650 8055,6650 8068,6663 v1(8068,6684) v1@8065,6684
  BottomLayer w8: v1(8035,7405) 8027.5,7397.5 8027.5,6724.5 v1(8068,6684)
D7: U1.19 U2.19 U3.19 U4.19 U5.13 U6.4 U7.27 | length 5226.3
  TopLayer w8: U6.4 5875,7928 6087,7716 6230,7716 6245,7701 ; U1.19 6552.5,6700 6577.5,6725 6670,6725 6679,6716 6811.5,6716 6827.5,6700 U2.19 7052.5,6700 7077.5,6725 7249.5,6725 7274.5,6700 U3.19 7552.5,6700 7577.5,6725 7675.5,6725 7738,6787.5 7767,6787.5 7822.5,6732 v1(7865,6732) 7897,6700 U4.19 ; U5.13 6451,7692 6427,7716 6260,7716 6245,7701 ; U7.27 v1(7900,7372) 7790.5,7372 7775,7387.5 7775,7482.5 7745,7512.5 7540,7512.5 7534.5,7518 7322,7518 7287,7553 7261,7553 7224,7516 7090,7516 7043.5,7562.5 6970,7562.5 6951.5,7581 6915,7581 6901.5,7567.5 6456.5,7567.5 6440,7584 6440,7612.5 6427.5,7625 6381,7625 6372,7616 6280.5,7616 6245,7651.5 6245,7701
  BottomLayer w8: v1(7865,6732) 7852.5,6744.5 7852.5,7356 7868.5,7372 v1(7900,7372)
GND: C1.1 C3.1 C4.1 C5.1 C6.1 C7.2 C8.2 J1.1 J2.5 J3.5 J4.1 J4.3 J4.5 J4.7 J4.9 J4.11 J4.13 J4.15 J4.17 J4.19 J4.21 J4.23 J4.25 J4.27 J4.29 J4.31 J4.33 J4.35 J4.37 J4.39 SW2.1 U1.14 U1.22 U2.14 U2.22 U3.14 U3.22 U4.14 U4.22 U5.29 U6.18 U6.19 U6.22 U6.23 U6.31 U7.7 U7.35 U8.8 U9.7 U10.7 U11.7 U12.8 U12.11 | length 2821.7
  TopLayer w12: C5.1 5500,6767 v1(5501,6768) ; C8.2 v1(5641,6840) ; C7.2 v1(5641,7190) ; U11.7 5767,8450 v1(5793,8476) ; U8.8 5780,6800 v1(5818,6838) ; U6.18 5774,7494 v1(5800,7520) 5824,7496 U6.19 ; C3.1 5800,8401 v1(5801,8402) ; v1(5819,7257) 5850,7288 SW2.1 ; U6.22 5975,7505 v1(5995,7525) 6025,7495 U6.23 ; U10.7 6169,8450 v1(6201,8418) 6200,8417 C6.1 ; U1.14 6192,6500 v1(6218,6526) ; U6.31 6405,7592 v1(6409,7596) ; C1.1 6375,7143.5 v1(6377.5,7141) ; v1(6431,6837.5) 6443.5,6850 U1.22 ; U12.8 v1(6605,8400) ; U2.14 6720,6500 v1(6725,6505) ; v1(6724,8500) U12.11 ; v1(6912,6854) 6916,6850 U2.22 ; C4.1 v1(6993,7225) ; U3.14 7180,6500 v1(7200,6480) ; U5.29 7241,7492 v1(7275,7526) ; U7.7 7450,7993 v1(7485,7958) ; v1(7405,6845) 7410,6850 U3.22 ; U4.14 7708,6500 v1(7734,6526) ; U9.7 7798,8450 v1(7840,8492) ; v1(7915,7795) 7918,7792 U7.35 ; U4.22 8056.5,6850 8098,6808.5 v1(8098,6800)
INT: R7.2 U5.16 U6.5 | length 2939.2
  TopLayer w8: U5.16 6416,7542 6390,7568 6277.5,7568 6205.5,7640 6106,7640 5824,7922 U6.5 5824,8188 5848.5,8212.5 7065.5,8212.5 7117.5,8160.5 7465.5,8160.5 7490,8185 R7.2
IORQ: U5.20 U6.36 | length 1010.2
  TopLayer w8: U6.36 6410,7842 6435,7817 6804,7817 v1(6820,7833) ; U5.20 6725,7485 6738,7498 v1(6815,7498)
  BottomLayer w8: v1(6815,7498) 6800.5,7512.5 6800.5,7825.5 6812.5,7837.5 6815.5,7837.5 v1(6820,7833)
M1: U5.27 U6.8 | length 3085.6
  TopLayer w8: U6.8 5673.5,7943 5652.5,7964 5652.5,8082.5 5805.5,8235.5 6990,8235.5 7079.5,8325 7240,8325 v1(7310,8255) ; U5.27 7075,7372 7097,7350 7130.5,7350 v1(7177.5,7397)
  BottomLayer w8: v1(7177.5,7397) 7177.5,7837.5 7227.5,7887.5 7227.5,8172.5 v1(7310,8255)
MEM0SEL: U1.20 U8.15 | length 826.7
  TopLayer w8: v1(5940,7075) 5965,7100 U8.15 ; v1(6339.5,6721.5) 6368,6750 U1.20
  BottomLayer w8: v1(5940,7075) 5940,7010 6228.5,6721.5 v1(6339.5,6721.5)
MEM1SEL: U2.20 U8.14 | length 1652.5
  TopLayer w8: U8.14 6040,7050 6052.5,7062.5 6052.5,7169.5 6070.5,7187.5 6190,7187.5 6277.5,7275 v1(6617,7275) ; v1(6777.5,6762.5) 6898.5,6762.5 6911,6750 U2.20
  BottomLayer w8: v1(6617,7275) 6652.5,7239.5 6652.5,6780 6670,6762.5 v1(6777.5,6762.5)
MEM2SEL: U3.20 U8.13 | length 1675.7
  TopLayer w8: U8.13 6061,7000 6086,7025 6315,7025 6352.5,6987.5 v1(6368.5,6987.5) ; v1(7364,6749) 7365,6750 U3.20
  BottomLayer w8: v1(6368.5,6987.5) 6656,6700 7315,6700 v1(7364,6749)
MEM3SEL: U4.20 U8.12 | length 4467.2
  TopLayer w8: U8.12 5927.5,6950 5852.5,6875 5682,6875 5652.5,6904.5 5652.5,7159 5706,7212.5 5733.5,7212.5 5771,7175 6002.5,7175 6052.5,7225 6202.5,7225 6315,7337.5 6686,7337.5 6701,7352.5 6701,7500 6726,7525 6852.5,7525 6900,7477.5 6900,7284.5 6922,7262.5 7177.5,7262.5 7240,7200 7890,7200 7965,7125 8042,7125 8065,7102 8065,7000 8090,6975 8208.5,6975 8227.5,6956 8227.5,6892 8244.5,6875 8298,6875 8327.5,6845.5 8327.5,6796 8306.5,6775 8115,6775 8090,6750 U4.20
NetC9_1: C9.1 R3.2 U9.12 | length 1691.9
  TopLayer w8: R3.2 7490,8490 7467.5,8512.5 7333.13,8512.5 7318.5,8527.13 7318.5,8688.5 7342.5,8712.5 7527.5,8712.5 7652.5,8837.5 8162.5,8837.5 8225,8775 8225,8685 8190,8650 U9.12
NetC9_2: C9.2 R4.1 U9.11 | length 1303.9
  TopLayer w8: R4.1 7350,8550 7335,8565 7335,8682.37 7347.63,8695 7572.5,8695 7633.53,8756.03 7678.97,8756.03 7710,8725 7800,8725 7925,8600 8195,8600 8280,8685 C9.2
NetC10_1: C10.1 R1.2 U9.2 | length 1562.3
  TopLayer w8: C10.1 6687.5,8337.5 7069.37,8337.5 7072.87,8341 7246.63,8341 7300.13,8287.5 7477.5,8287.5 v1(7490,8300) R1.2 ; v1(7660,8725) 7675,8725 7700,8700 U9.2
  BottomLayer w8: v1(7490,8300) 7545,8300 7660,8415 v1(7660,8725)
NetC10_2: C10.2 R2.1 U9.3 | length 1504
  TopLayer w8: C10.2 v1(6790,8300) ; R2.1 7400,8610 7415,8595 7562,8595 v1(7629.5,8662.5) 7642,8650 U9.3
  BottomLayer w8: v1(6790,8300) 7152.5,8662.5 v1(7629.5,8662.5)
NetJ2_2: J2.2 U10.1 | length 744.2
  TopLayer w8: J2.2 5640,8580 5640,8607 5658,8625 5752.5,8625 5852.5,8725 6015,8725 6040,8750 U10.1
NetJ2_3: J2.3 U11.3 | length 241.4
  TopLayer w8: J2.3 5600,8650 U11.3
NetJ3_2: J3.2 U10.4 | length 1292.4
  TopLayer w8: J3.2 5654,7844 v1(5654,7908) ; v1(5818.5,8547) 5846.5,8575 6027.5,8575 6052.5,8600 U10.4
  BottomLayer w8: v1(5654,7908) 5690,7944 5690,8418.5 v1(5818.5,8547)
NetJ3_3: J3.3 U11.6 | length 802.2
  TopLayer w8: J3.3 5590,7890 5590,8423 5667,8500 U11.6
NetR1_1: R1.1 U9.1 XTAL1.1 | length 1750.2
  TopLayer w8: v1(7340,8433) 7340,8370 7360,8350 R1.1 ; v1(7640,8150) 7840,8150 7900,8210 XTAL1.1 ; U9.1 v1(7820,8750)
  BottomLayer w8: v1(7340,8433) 7340,8284 7361.5,8262.5 7527.5,8262.5 v1(7640,8150) 7685,8195 7685,8615 v1(7820,8750)
NetR2_2: R2.2 U9.4 U9.5 XTAL1.2 | length 1461.6
  TopLayer w8: R2.2 7572,8650 7617,8695 7645,8695 7665,8675 7802.8,8675 7845.07,8632.73 7845.07,8600 ; U9.5 U9.4 7845.07,8600 ; XTAL1.2 7800,8257 7818,8275 8052.5,8275 8102.5,8325 8102.5,8556 8083.5,8575 7870.07,8575 7845.07,8600
NetR3_1: R3.1 U9.13 XTAL2.1 | length 1012.6
  TopLayer w8: R3.1 7400,8413 v1(7415,8398) ; v1(7544,8364) 7558,8350 XTAL2.1 v1(7890,8350) ; v1(7925,8700) U9.13
  BottomLayer w8: v1(7415,8398) 7425.5,8387.5 7520.5,8387.5 v1(7544,8364) ; v1(7890,8350) 7890,8665 v1(7925,8700)
NetR4_2: R4.2 U9.9 U9.10 XTAL2.2 | length 882.8
  TopLayer w8: R4.2 7594,8550 7615,8529 7615,8527.5 7617.5,8525 7865,8525 7890,8550 U9.10 U9.9 8065,8500 8077.5,8487.5 8077.5,8369.5 8058,8350 XTAL2.2
NetSW1_9: SW1.9 SW1.10 SW1.11 SW1.12 SW1.13 SW1.14 SW1.15 SW1.16 U6.13 U6.14 U6.27 | length 3885.9
  TopLayer w8: U6.13 U6.14 v1(5817,7642) 5900,7559 5900,7387.5 5877.5,7365 5877.5,7300 5895.5,7282 6182,7282 6225,7325 U6.27 ; v1(5852.5,8675) 6177.5,8675 ; 6175,8675 6285,8785 7235,8785 7245,8775 SW1.9
  BottomLayer w8: v1(5817,7642) 5852.5,7677.5 v1(5852.5,8675)
NetU5_19: U5.19 U8.4 U8.5 | length 1598.1
  TopLayer w8: U8.5 U8.4 5825,7000 5865,7040 v1(5865,7062.5) ; v1(6027.5,7312.5) 6101,7386 6101,7521 6125,7545 6205,7545 6251,7499 6251,7387.5 6263.5,7375 6290,7375 6340,7425 6527.5,7425 6577.5,7375 6661.5,7375 6674,7387.5 U5.19
  BottomLayer w8: v1(5865,7062.5) 5865,7150 v1(6027.5,7312.5)
NetU6_12: U6.12 U10.3 | length 1603.1
  TopLayer w8: v1(5640,8525) 5765,8525 5777.5,8512.5 5827.5,8512.5 5840,8525 6010,8525 6060,8575 6165,8575 6185,8595 6185,8635 6170,8650 U10.3 ; v1(5652.5,7725) 5669.5,7742 U6.12
  BottomLayer w8: v1(5640,8525) 5627,8512 5627,7750.5 v1(5652.5,7725)
NetU6_15: U6.15 U11.2 | length 1663.5
  TopLayer w8: v1(5452.5,7525) 5602.5,7525 5669.5,7592 U6.15 ; v1(5452.5,8612.5) 5538.5,8612.5 5626,8700 U11.2
  BottomLayer w8: v1(5452.5,7525) v1(5452.5,8612.5)
NetU6_26: U6.26 U11.4 U11.5 | length 1816.1
  TopLayer w8: U11.5 5760,8550 5775,8565 5775,8590 ; U11.4 5765,8600 5775,8590 ; v1(6027.5,8625) 5865,8625 5840,8600 5785,8600 5775,8590 ; U6.26 v1(6175,7500)
  BottomLayer w8: v1(6027.5,8625) 6065,8587.5 6065,8057.5 5998,7990.5 5998,7962.5 6012.5,7948 6110,7948 6127.5,7930.5 6127.5,7547.5 v1(6175,7500)
NetU6_28: U6.28 U10.6 | length 1381.2
  TopLayer w8: v1(6027.5,8475) 6052.5,8500 U10.6 ; v1(6065,7550) 6090,7575 6200,7575 6275,7500 U6.28
  BottomLayer w8: v1(6027.5,8475) 5977.5,8425 5977.5,7637.5 v1(6065,7550)
PA0: J4.16 U7.4 | length 1038.9
  TopLayer w8: U7.4 7550,7850 7700,7700 7878,7700 7895,7717 8088.5,7717 8146.5,7775 8225,7775 J4.16
PA1: J4.14 U7.3 | length 800.4
  TopLayer w8: U7.3 7600,7995 7727,7868 8232,7868 J4.14
PA2: J4.12 U7.2 | length 711.5
  TopLayer w8: U7.2 7650,8002 7685,7967 8144.5,7967 8152.5,7975 8190,7975 8240,7925 J4.12
PA3: J4.10 U7.1 | length 762.4
  TopLayer w8: U7.1 7700,8092 7720.5,8112.5 7882.5,8112.5 7906.89,8136.89 8076.89,8136.89 8115,8175 8208.5,8175 8227.5,8156 8227.5,8105 8275,8057.5 J4.10
PA4: J4.8 U7.40 | length 644.4
  TopLayer w8: U7.40 8075,8050 8100,8075 8208,8075 8227.5,8055.5 8227.5,7996 8248.5,7975 8306.5,7975 8327.5,7996 8327.5,8108 8310.5,8125 J4.8
PA5: J4.6 U7.39 | length 1147.7
  TopLayer w8: U7.39 7694,7993 7675,8012 7675,8108 7701,8134 7874,8134 7895,8155 8030.5,8155 8150.5,8275 8262.5,8275 8275,8262.5 J4.6
PA6: J4.4 U7.38 | length 588.9
  TopLayer w8: U7.38 8055,7943 8060.5,7937.5 v1(8083,7937.5)
  BottomLayer w8: v1(8083,7937.5) 8120.5,7975 8195,7975 8227.5,8007.5 8227.5,8277.5 J4.4
PA7: J4.2 U7.37 | length 891.3
  TopLayer w8: U7.37 8070,7892 8078,7900 v1(8113,7900)
  BottomLayer w8: v1(8113,7900) 8138,7875 8302.5,7875 8327.5,7900 8327.5,8372.5 J4.2
PB0: J4.26 U7.18 | length 1237.4
  TopLayer w8: U7.18 7449,7251 7475,7225 7532.5,7225 7545,7237.5 8052.5,7237.5 8127.5,7162.5 8127.5,7100 8152.5,7075 8202.5,7075 8227.5,7100 8227.5,7177.5 J4.26
PB1: J4.28 U7.19 | length 1223.3
  TopLayer w8: U7.19 7499,7370 7594,7275 7917.63,7275 7955.13,7312.5 8001.5,7312.5 8132,7182 8202,7182 8218,7198 8218,7259 8234,7275 8298,7275 8318,7255 8318,7168 J4.28
PB2: J4.30 U7.20 | length 1079.9
  TopLayer w8: U7.20 7550,7372 7631,7291 7911,7291 7954.5,7334.5 8084.5,7334.5 v1(8094,7325)
  BottomLayer w8: v1(8094,7325) 8127.5,7291.5 8127.5,7100 8152.5,7075 8225,7075 J4.30
PB3: J4.32 U7.21 | length 1414.6
  TopLayer w8: U7.21 7600,7365 7658,7307 7902.5,7307 7946,7350.5 8056.5,7350.5 8065,7359 8106,7359 8127.5,7337.5 8127.5,7294.5 8147,7275 8195,7275 8227.5,7307.5 8227.5,7340.5 8255,7368 8299.5,7368 8334,7333.5 8334,6984 J4.32
PB4: J4.34 U7.22 | length 1101.7
  TopLayer w8: U7.22 7650,7360 7665,7345 v1(7702.5,7345) ; v1(7752.5,6987.5) 7765,6975 8060.5,6975 8160.5,6875 8190,6875 8215,6850 8250,6850 J4.34
  BottomLayer w8: v1(7702.5,7345) 7702.5,7037.5 v1(7752.5,6987.5)
PB5: J4.36 U7.23 | length 1713.9
  TopLayer w8: U7.23 7700,7390 7756,7334 v1(7889,7334)
  BottomLayer w8: v1(7889,7334) 7877.5,7322.5 7877.5,7007.5 7902.5,6982.5 7902.5,6700 7865,6662.5 7850.5,6662.5 7838,6650 7838,6608.5 7984,6462.5 8106,6462.5 8132,6488.5 8132,6546 8161,6575 8195,6575 8227.5,6607.5 8227.5,6677.5 J4.36
PB6: J4.38 U7.24 | length 2018.9
  TopLayer w8: v1(7677.5,7375) 7677.5,7386 7676,7387.5 7676,7475 7697.5,7496.5 7733.5,7496.5 7750,7480 U7.24
  BottomLayer w8: v1(7677.5,7375) 7640,7337.5 7640,6912.5 7779.5,6773 7779.5,6748 7652.5,6621 7652.5,6484 7692,6444.5 8185,6444.5 8227.5,6487 8227.5,6577.5 J4.38
PB7: J4.40 U7.25 | length 2536.2
  TopLayer w8: v1(7567,7540) 7765,7540 7800,7505 U7.25
  BottomLayer w8: v1(7567,7540) 7567,7607 7835,7875 8017,7875 8117,7775 8208.5,7775 8227.5,7756 8227.5,7692 8244.5,7675 8298,7675 8334,7639 8334,6584 J4.40
PC0: J4.18 U7.14 | length 937.3
  TopLayer w8: U7.14 7851,7642 7875,7618 8053,7618 8110,7675 8225,7675 J4.18
PC1: J4.20 U7.15 | length 985.3
  TopLayer w8: U7.15 7465,7592 7498,7625 7843.5,7625 7950.5,7518 8102.5,7518 8159.5,7575 8225,7575 J4.20
PC2: J4.22 U7.16 | length 1048.3
  TopLayer w8: U7.16 7515,7542 7544.5,7571.5 7838.5,7571.5 7926,7484 7926,7397 7948,7375 8215,7375 8227.5,7387.5 8237.5,7387.5 J4.22
PC3: J4.24 U7.17 | length 1807.8
  TopLayer w8: U7.17 7457,7492 7474,7475 7474,7340 7555,7259 7952.5,7259 v1(7976,7282.5)
  BottomLayer w8: v1(7976,7282.5) 7976,7632 8019,7675 8196.5,7675 8227.5,7644 8227.5,7497.5 8250,7475 8305.5,7475 8318,7462.5 8318,7368 J4.24
PPISEL: U7.6 U8.10 | length 2478.1
  TopLayer w8: U8.10 6052.5,6850 6077.5,6825 v1(6310,6825) ; v1(6627.5,7925) 6676.5,7876 7037,7876 7080,7919 7230.5,7919 7349,8037.5 7449,8037.5 U7.6
  BottomLayer w8: v1(6310,6825) 6310,7170 6577.5,7437.5 6577.5,7875 v1(6627.5,7925)
RAWBAUD: U9.8 U12.10 | length 1393.3
  TopLayer w8: U12.10 6877.5,8450 6902.5,8475 7086,8475 7186,8375 7290.5,8375 7353,8312.5 7437,8312.5 7442,8317.5 7442,8375 7458.5,8391.5 7656.5,8391.5 7677.5,8412.5 7890,8412.5 7927.5,8450 U9.8
RD: U5.21 U6.32 U7.5 | length 2101.1
  TopLayer w8: U6.32 6476.5,7642 6502.5,7616 v1(6749,7616) ; v1(6750,7360) 6775,7385 U5.21 ; v1(7040,8150) 7052.5,8137.5 7069.5,8137.5 7078.5,8128.5 7468.5,8128.5 7499,8098 U7.5
  BottomLayer w8: v1(6750,7360) 6749,7361 v1(6749,7616) 6765,7632 6765,7882 6833.8,7950.8 7004.2,7950.8 7005,7950 7050,7950 7065,7965 7065,8125 v1(7040,8150)
RESET: C8.1 R6.2 SW2.2 U5.26 U6.21 | length 3815.8
  TopLayer w8: C8.1 5434,7025 5415,7044 5415,7575 5465,7625 5511.5,7625 5652.5,7766 5827,7766 5993,7600 ; SW2.2 5905,7362.5 5925,7382.5 5925,7532 5993,7600 ; U5.26 7025,7516 7003.5,7537.5 6950.5,7537.5 v1(6938,7550) 6659.5,7550 6627.5,7518 6290,7518 6208,7600 5993,7600 ; v1(7186,8298) 7202.5,8281.5 7202.5,8252.5 7205,8250 R6.2
  BottomLayer w8: v1(6938,7550) 6940,7552 6940,7812.5 7202.5,8075 7202.5,8281.5 v1(7186,8298)
SIOSEL: U6.35 U8.11 | length 1265.4
  TopLayer w8: U8.11 6052.5,6900 6077.5,6925 6251,6925 v1(6267,6941) ; v1(6230,7791) 6231,7792 U6.35
  BottomLayer w8: v1(6230,7791) 6277.5,7743.5 6277.5,6951.5 v1(6267,6941)
VCC: C1.2 C3.2 C4.2 C5.2 C6.2 C7.1 J1.2 R5.1 R6.1 R7.1 U1.1 U1.28 U2.1 U2.28 U3.26 U3.28 U4.26 U4.28 U5.11 U5.17 U5.24 U5.25 U6.6 U6.9 U7.26 U8.6 U8.16 U9.14 U10.14 U12.16 | length 2613.1
  TopLayer w12: C7.1 5618,7375 v1(5641,7352) ; C5.2 v1(5555,6768) ; U6.9 v1(5783,7892) ; U8.6 5804,6900 v1(5818,6914) ; U6.6 5774,8124 v1(5775,8125) ; C3.2 v1(5923,8350) ; v1(5902,7096) 5902,7122 5930,7150 U8.16 ; U1.1 6194,7150 v1(6218,7174) ; C6.2 v1(6255,8418) ; v1(6277,8708) 6277,8708.5 6318.5,8750 U10.14 ; v1(6412,7108) 6454,7150 U1.28 ; C1.2 v1(6498,7225) ; U5.17 6642,7492 v1(6644,7494) ; U5.11 6631,7792 v1(6665,7758) ; U2.1 6694,7150 v1(6718,7174) ; U12.16 6870,8750 v1(6875,8745) ; C4.2 v1(6870,7173) 6893,7150 6906,7150 U2.28 ; U5.24 6925,7485 6927.5,7487.5 v1(6927.5,7512) 6948,7512 6975,7485 U5.25 ; R6.1 7150,8206 v1(7165,8191) ; v1(7333,8750) R5.1 ; R7.1 7400,8208 v1(7420,8188) ; v1(7412,7140) 7422,7150 U3.28 ; v1(7428,7048) 7430,7050 U3.26 ; U7.26 v1(7850,7520) ; v1(7912,7070) 7932,7050 U4.26 ; v1(7925,8750) U9.14 ; U4.28 8072,7150 v1(8098,7124)
WR: U1.27 U2.27 U3.27 U4.27 U5.22 U7.36 | length 2688.9
  TopLayer w8: U1.27 6552.5,7100 6577.5,7125 6825,7125 ; U5.22 6825,7125 ; v1(7940,7837.5) 7944.5,7842 U7.36 ; U4.27 v1(7940,7100) 7915,7125 7577.5,7125 7552.5,7100 U3.27 7390,7100 7365,7125 7077.5,7125 7052.5,7100 U2.27 6850,7100 6825,7125
  BottomLayer w8: v1(7940,7100) 7940,7400 7952.5,7412.5 7952.5,7825 v1(7940,7837.5)
pads on no net: J2.1 J2.4 J2.6 J2.7 J2.8 J2.9 J3.1 J3.4 J3.6 J3.7 J3.8 J3.9 U1.26 U2.26 U3.1 U4.1 U5.18 U5.23 U5.28 U5.41 U5.42 U5.43 U5.44 U6.7 U6.10 U6.11 U6.16 U6.17 U6.24 U6.25 U6.29 U6.30 U6.41 U6.42 U6.43 U6.44 U7.10 U7.11 U7.12 U7.13 U7.41 U7.42 U7.43 U7.44 U8.7 U8.9 U10.2 U10.5 U10.8 U10.9 U10.10 U10.11 U10.12 U10.13 U11.8 U11.9 U11.10 U11.11 U11.12 U11.13 U12.1 U12.6 U12.7 U12.9

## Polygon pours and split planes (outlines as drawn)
GND on GroundPlane (split plane): 5340,6440 8310,6440 8310,8860 5340,8860
-12 on PowerNetsPlane (split plane): 5340,6440 5510,6440 5510,6600 5410,6600 5400,6610 5400,7390 5402.93,7397.07 5490,7484.14 5490,8700 5500,8710 5630,8710 5630,8860 5340,8860
+12 on PowerNetsPlane (split plane): 5420,6620 5520,6620 5530,6610 5530,6440 5670,6440 5670,6700 5500,6700 5490,6710 5490,7320 5492.93,7327.07 5600,7434.14 5600,8580 5610,8590 5920,8590 5920,8860 5650,8860 5650,8700 5640,8690 5510,8690 5510,7480 5507.07,7472.93 5420,7385.86
VCC on PowerNetsPlane (split plane): 5510,6720 5680,6720 5690,6710 5690,6440 8310,6440 8310,8860 5940,8860 5940,8580 5930,8570 5620,8570 5620,7430 5617.07,7422.93 5510,7315.86

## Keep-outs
KeepOutLayer:
  lines w8: 5325,6425 5325,8875 8350,8875 8350,6425 5325,6425

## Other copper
TopLayer:
  text ".GTL" at 9680,6290 h90
BottomLayer:
  text ".GBL" at 9680,6290 h90
GroundPlane (plane layer: these items are gaps in the copper):
  text ".GP1" at 9680,6290 h90
PowerNetsPlane (plane layer: these items are gaps in the copper):
  lines w20: 5520,6420 5520,6610 5410,6610 5410,7390 5500,7480 5500,8700 5640,8700 5640,8880 ; 5680,6420 5680,6710 5500,6710 5500,7320 5610,7430 5610,8580 5930,8580 5930,8880
  text ".GP2" at 9680,6290 h90

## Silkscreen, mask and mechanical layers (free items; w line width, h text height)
TopOverlay:
  text ".GTO" at 9680,6290 h90
TopPaste:
  text ".GTP" at 10200,6200 h90
BottomPaste:
  text ".GBP" at 10200,6200 h90
TopSolder:
  text ".GTS" at 10200,6200 h90
BottomSolder:
  text ".GBS" at 10200,6200 h90
Mechanical1:
  the board outline again, w8
Mechanical4:
  text ".LAYER_NAME" at 8620,6279.99 h90
  text "Z80 Processor (SMT)" at 11590,4022.88 h130
Mechanical16:
  drawing of 1690 lines, arcs and shapes, not listed
  text "1" at 4427,10465 h70
  text "2" at 7287,10465 h70
  text "3" at 10167,10465 h70
  text "4" at 13037,10465 h70
  text "A" at 3075,9559 h70
  text "A" at 14375,9559 h70
  text "B" at 3075,7667 h70
  text "B" at 14375,7667 h70
  text "C" at 3075,5757 h70
  text "C" at 14375,5757 h70
  text "ENGINEER:" at 9850,4300 h45
  text "TITLE:" at 11350,4300 h45
  text "PCB DESIGNER:" at 9850,4005 h45
  text "n" at 9076,3928 h35
  text "n" at 9076,3928 h35
  text "T" at 8550,3927 h35
  text "T" at 8550,3927 h35
  text "h" at 8595,3927 h35
  text "h" at 8595,3927 h35
  text "i" at 8635.33,3927 h35
  text "i" at 8635.33,3927 h35
  text "n" at 8664,3927 h35
  text "n" at 8664,3927 h35
  text "k" at 8710,3927 h35
  text "k" at 8710,3927 h35
  text "i" at 8770.67,3927 h35
  text "i" at 8770.67,3927 h35
  text "t" at 8796.67,3927 h35
  text "t" at 8796.67,3927 h35
  text "," at 8827.67,3926.67 h35
  text "," at 8827.67,3926.67 h35
  text "D" at 8880,3927 h35
  text "D" at 8880,3927 h35
  text "e" at 8927,3927 h35
  text "e" at 8927,3927 h35
  text "s" at 8968,3927 h35
  text "s" at 8968,3927 h35
  text "i" at 9000.33,3927 h35
  text "i" at 9000.33,3927 h35
  text "g" at 9029,3926.66 h35
  text "g" at 9029,3926.66 h35
  text "i" at 9140.33,3927 h35
  text "i" at 9140.33,3927 h35
  text "t" at 9164.67,3927 h35
  text "t" at 9164.67,3927 h35
  text "," at 9195.67,3926.67 h35
  text "," at 9195.67,3926.67 h35
  text "B" at 9246,3927 h35
  text "B" at 9246,3927 h35
  text "u" at 9294,3927 h35
  text "u" at 9294,3927 h35
  text "i" at 9331.33,3927 h35
  text "i" at 9331.33,3927 h35
  text "l" at 9361,3927 h35
  text "l" at 9361,3927 h35
  text "d" at 9383,3927 h35
  text "d" at 9383,3927 h35
  text "i" at 9447.67,3927 h35
  text "i" at 9447.67,3927 h35
  text "t" at 9473.67,3927 h35
  text "t" at 9473.67,3927 h35
  text "D" at 3075,3867 h70
  text "D" at 14375,3867 h70
  text "DATE:" at 9850,3700 h45
  text "PART NO.:" at 11350,3700 h45
  text "REV:" at 13450,3700 h45
  text "Altium Limited" at 8550,3600 h70
  text ".PRINT_DATE" at 9900,3580 h70
  text "12a Rodborough Rd" at 8550,3500 h70
  text "Frenchs Forest" at 8550,3400 h70
  text "FILE NAME:" at 9850,3400 h45
  text "DWG NO:" at 11350,3400 h45
  text "SCALE:" at 13450,3400 h45
  text "NSW 2086" at 8550,3300 h70
  text ".PCB_FILE_NAME_NO_PATH" at 9900,3280 h70
  text "1" at 4427,3065 h70
  text "2" at 7287,3065 h70
  text "3" at 10167,3065 h70
  text "4" at 13037,3065 h70
DrillDrawing:
  text ".LEGEND" at 8620,6429.99 h90

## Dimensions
5300,6400 to 5300,8900 on Mechanical4
5300,6400 to 8350,6400 on Mechanical4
